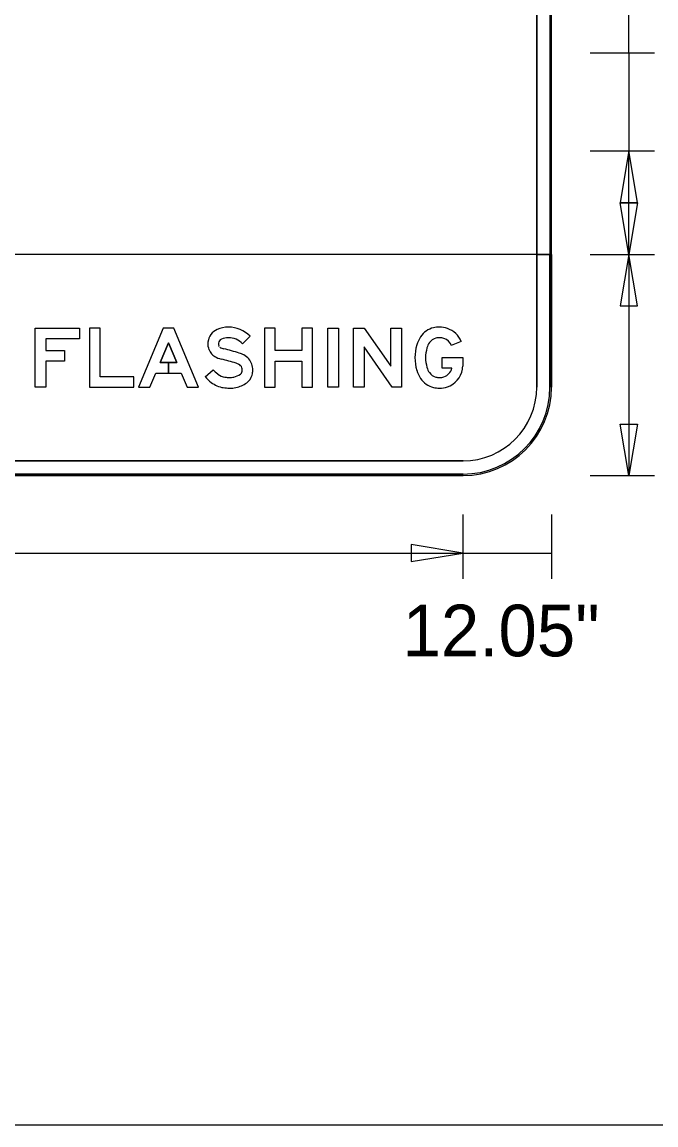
# Model space of a CAD drawing. Extents: x 17890071 to 17890754, y 17897628 to 17897992.
# Drawn here: x 17890204.8 to 17890211.96, y 17897794.28 to 17897806.75 of the extents above; entities that cross this region are included whole.
import ezdxf

# ---------------------------------------------------------------- set-up
doc = ezdxf.new("R2010")
doc.units = 0
for name, color, linetype in [('GSBWFill', 7, 'Continuous'), ('GSColorFill', 7, 'Continuous'), ('GSDims', 7, 'Continuous'), ('GSOutline', 7, 'Continuous'), ('SheetLinesMisc2_dp', 7, 'Continuous')]:
    doc.layers.add(name, color=color, linetype=linetype)

msp = doc.modelspace()

# ---------------------------------------------------------------- linework, layer by layer
at = {"layer": 'GSBWFill'}
for p, q in [((17890210.615, 17897810.621), (17890210.615, 17897802.621)), ((17890210.782, 17897802.621), (17890210.782, 17897810.621)), ((17890210.782, 17897804.121), (17890190.782, 17897804.121)), ((17890210.615, 17897803.954), (17890210.615, 17897804.121)), ((17890210.615, 17897804.121), (17890210.782, 17897804.121)), ((17890210.782, 17897804.121), (17890210.782, 17897802.621)), ((17890210.782, 17897802.621), (17890210.782, 17897804.121)), ((17890210.615, 17897802.621), (17890210.615, 17897803.954)), ((17890191.782, 17897801.788), (17890209.782, 17897801.788)), ((17890209.782, 17897801.788), (17890191.783, 17897801.788)), ((17890209.782, 17897801.621), (17890191.782, 17897801.621)), ((17890191.782, 17897801.621), (17890209.782, 17897801.621)), ((17890191.783, 17897801.621), (17890209.782, 17897801.621))]:
    msp.add_line(p, q, dxfattribs=at)
for points in [[(17890205.065, 17897802.914), (17890205.065, 17897802.621), (17890204.945, 17897802.621), (17890204.945, 17897803.288), (17890205.445, 17897803.288), (17890205.445, 17897803.168), (17890205.065, 17897803.168), (17890205.065, 17897803.034), (17890205.275, 17897803.034), (17890205.275, 17897802.914)], [(17890206.058, 17897802.621), (17890206.058, 17897802.738), (17890205.678, 17897802.738), (17890205.678, 17897803.288), (17890205.558, 17897803.288), (17890205.558, 17897802.621)], [(17890206.545, 17897802.898), (17890206.452, 17897802.898), (17890206.452, 17897802.778), (17890206.596, 17897802.778), (17890206.662, 17897802.621), (17890206.792, 17897802.621), (17890206.512, 17897803.288), (17890206.392, 17897803.288), (17890206.112, 17897802.621), (17890206.242, 17897802.621), (17890206.308, 17897802.778), (17890206.452, 17897802.778), (17890206.452, 17897802.898), (17890206.358, 17897802.898), (17890206.452, 17897803.121)], [(17890207.958, 17897803.034), (17890207.658, 17897803.034), (17890207.658, 17897803.288), (17890207.538, 17897803.288), (17890207.538, 17897802.621), (17890207.658, 17897802.621), (17890207.658, 17897802.914), (17890207.958, 17897802.914), (17890207.958, 17897802.621), (17890208.078, 17897802.621), (17890208.078, 17897803.288), (17890207.958, 17897803.288)], [(17890208.252, 17897802.621), (17890208.252, 17897803.288), (17890208.372, 17897803.288), (17890208.372, 17897802.621)], [(17890209.085, 17897803.288), (17890209.085, 17897802.621), (17890208.982, 17897802.621), (17890208.665, 17897803.078), (17890208.665, 17897802.621), (17890208.545, 17897802.621), (17890208.545, 17897803.288), (17890208.665, 17897803.288), (17890208.965, 17897802.856), (17890208.965, 17897803.288)]]:
    msp.add_lwpolyline(points, close=True, dxfattribs=at)
for points in [[(17890207.374, 17897803.196), (17890207.289, 17897803.112)], [(17890209.76, 17897803.136), (17890209.649, 17897803.091)], [(17890209.655, 17897802.834), (17890209.545, 17897802.834), (17890209.545, 17897802.954), (17890209.778, 17897802.954), (17890209.778, 17897802.858)], [(17890206.865, 17897802.739), (17890206.956, 17897802.817)]]:
    msp.add_lwpolyline(points, dxfattribs=at)
for centre, radius, start, end in [((17890207.071, 17897803.113), 0.174, 113.3248, 174.1421), ((17890207.128, 17897802.981), 0.318, 90, 113.3248), ((17890207.128, 17897802.954), 0.345, 44.4342, 90), ((17890209.503, 17897803.058), 0.24, 103.1315, 146.7742), ((17890209.514, 17897803.01), 0.289, 90, 103.1315), ((17890209.514, 17897803.019), 0.28, 71.2015, 90), ((17890209.521, 17897803.039), 0.259, 22.0367, 71.2015), ((17890207.087, 17897803.111), 0.191, 174.1421, 201.2247), ((17890207.071, 17897803.113), 0.0543, 113.3248, 174.1421), ((17890207.087, 17897803.111), 0.0706, 174.1421, 201.2247), ((17890207.049, 17897803.096), 0.029, 201.2247, 240.1812), ((17890207.128, 17897802.981), 0.198, 90, 113.3248), ((17890207.128, 17897802.954), 0.225, 44.4342, 90), ((17890209.743, 17897802.954), 0.505, 163.4624, 180), ((17890209.592, 17897802.999), 0.348, 146.7742, 163.4624), ((17890209.592, 17897802.999), 0.228, 146.7742, 163.4624), ((17890209.503, 17897803.058), 0.12, 103.1315, 146.7742), ((17890209.514, 17897803.01), 0.169, 90, 103.1315), ((17890209.514, 17897803.019), 0.16, 71.2015, 90), ((17890209.521, 17897803.039), 0.139, 22.0367, 71.2015), ((17890207.049, 17897803.096), 0.149, 201.2247, 240.1812), ((17890207.117, 17897803.217), 0.288, 240.1812, 256.1067), ((17890207.117, 17897803.217), 0.168, 240.1812, 256.1067), ((17890206.3, 17897799.913), 3.236, 72.8961, 76.1067), ((17890207.158, 17897802.7), 0.32, 63.0108, 72.8961), ((17890207.222, 17897802.826), 0.178, 39.5561, 63.0108), ((17890209.743, 17897802.954), 0.505, 180, 196.5376), ((17890209.743, 17897802.954), 0.385, 163.4624, 180), ((17890209.743, 17897802.954), 0.385, 180, 196.5376), ((17890206.3, 17897799.913), 3.116, 72.8961, 76.1067), ((17890207.158, 17897802.7), 0.2, 63.0108, 72.8961), ((17890207.222, 17897802.826), 0.0579, 39.5561, 63.0108), ((17890207.206, 17897802.813), 0.0794, 0, 39.5561), ((17890207.206, 17897802.813), 0.199, 0, 39.5561), ((17890209.592, 17897802.91), 0.228, 196.5376, 213.2258), ((17890209.521, 17897802.869), 0.139, 288.7985, 345.418), ((17890209.58, 17897802.858), 0.198, 349.6765, 0), ((17890207.216, 17897803.043), 0.464, 220.8202, 232.6492), ((17890207.216, 17897803.043), 0.344, 220.8202, 232.6492), ((17890207.12, 17897802.916), 0.185, 232.6492, 260.7349), ((17890207.14, 17897803.04), 0.31, 260.7349, 270), ((17890207.14, 17897802.974), 0.245, 270, 281.6446), ((17890207.15, 17897802.926), 0.196, 281.6446, 306.0677), ((17890207.239, 17897802.804), 0.045, 306.0677, 343.4972), ((17890207.21, 17897802.813), 0.0746, 343.4972, 0), ((17890207.239, 17897802.804), 0.165, 306.0677, 343.4972), ((17890207.21, 17897802.813), 0.195, 343.4972, 0), ((17890209.592, 17897802.91), 0.348, 196.5376, 213.2258), ((17890209.503, 17897802.851), 0.24, 213.2258, 256.8685), ((17890209.503, 17897802.851), 0.12, 213.2258, 256.8685), ((17890209.514, 17897802.899), 0.169, 256.8685, 270), ((17890209.514, 17897802.889), 0.16, 270, 288.7985), ((17890209.521, 17897802.869), 0.259, 288.7985, 349.6765), ((17890207.12, 17897802.916), 0.305, 232.6492, 260.7349), ((17890207.14, 17897803.04), 0.43, 260.7349, 270), ((17890207.14, 17897802.974), 0.365, 270, 281.6446), ((17890207.15, 17897802.926), 0.316, 281.6446, 306.0677), ((17890209.514, 17897802.899), 0.289, 256.8685, 270), ((17890209.514, 17897802.889), 0.28, 270, 288.7985), ((17890209.782, 17897802.621), 1, 270, 0), ((17890209.782, 17897802.621), 0.833, 270, 0), ((17890209.782, 17897802.621), 1, 270, 0), ((17890209.782, 17897802.621), 0.833, 270, 0), ((17890209.782, 17897802.621), 1, 270, 0)]:
    msp.add_arc(centre, radius, start, end, dxfattribs=at)
at = {"layer": 'GSColorFill'}
for p, q in [((17890210.615, 17897810.621), (17890210.615, 17897802.621)), ((17890210.765, 17897810.621), (17890210.765, 17897802.621)), ((17890210.782, 17897802.621), (17890210.782, 17897810.621)), ((17890210.782, 17897802.621), (17890210.782, 17897810.621)), ((17890210.782, 17897802.621), (17890210.782, 17897810.621)), ((17890210.782, 17897804.121), (17890190.782, 17897804.121)), ((17890210.615, 17897803.954), (17890210.615, 17897804.121)), ((17890210.615, 17897804.121), (17890210.782, 17897804.121)), ((17890210.765, 17897804.104), (17890210.765, 17897804.121)), ((17890210.765, 17897804.121), (17890210.782, 17897804.121)), ((17890210.765, 17897802.621), (17890210.765, 17897804.104)), ((17890210.782, 17897802.621), (17890210.782, 17897804.121)), ((17890210.782, 17897804.121), (17890210.782, 17897802.621)), ((17890210.782, 17897804.121), (17890210.782, 17897802.621)), ((17890210.615, 17897802.621), (17890210.615, 17897803.954)), ((17890191.782, 17897801.788), (17890209.782, 17897801.788)), ((17890209.782, 17897801.788), (17890191.783, 17897801.788)), ((17890209.782, 17897801.638), (17890191.782, 17897801.638)), ((17890191.782, 17897801.638), (17890209.782, 17897801.638)), ((17890191.782, 17897801.621), (17890209.782, 17897801.621)), ((17890191.782, 17897801.621), (17890209.782, 17897801.621)), ((17890191.782, 17897801.621), (17890209.782, 17897801.621)), ((17890209.782, 17897801.621), (17890191.782, 17897801.621)), ((17890209.782, 17897801.621), (17890191.782, 17897801.621)), ((17890191.783, 17897801.621), (17890209.782, 17897801.621))]:
    msp.add_line(p, q, dxfattribs=at)
for points in [[(17890205.065, 17897802.914), (17890205.065, 17897802.621), (17890204.945, 17897802.621), (17890204.945, 17897803.288), (17890205.445, 17897803.288), (17890205.445, 17897803.168), (17890205.065, 17897803.168), (17890205.065, 17897803.034), (17890205.275, 17897803.034), (17890205.275, 17897802.914)], [(17890206.058, 17897802.621), (17890206.058, 17897802.738), (17890205.678, 17897802.738), (17890205.678, 17897803.288), (17890205.558, 17897803.288), (17890205.558, 17897802.621)], [(17890206.545, 17897802.898), (17890206.452, 17897802.898), (17890206.452, 17897802.778), (17890206.596, 17897802.778), (17890206.662, 17897802.621), (17890206.792, 17897802.621), (17890206.512, 17897803.288), (17890206.392, 17897803.288), (17890206.112, 17897802.621), (17890206.242, 17897802.621), (17890206.308, 17897802.778), (17890206.452, 17897802.778), (17890206.452, 17897802.898), (17890206.358, 17897802.898), (17890206.452, 17897803.121)], [(17890207.958, 17897803.034), (17890207.658, 17897803.034), (17890207.658, 17897803.288), (17890207.538, 17897803.288), (17890207.538, 17897802.621), (17890207.658, 17897802.621), (17890207.658, 17897802.914), (17890207.958, 17897802.914), (17890207.958, 17897802.621), (17890208.078, 17897802.621), (17890208.078, 17897803.288), (17890207.958, 17897803.288)], [(17890208.252, 17897802.621), (17890208.252, 17897803.288), (17890208.372, 17897803.288), (17890208.372, 17897802.621)], [(17890209.085, 17897803.288), (17890209.085, 17897802.621), (17890208.982, 17897802.621), (17890208.665, 17897803.078), (17890208.665, 17897802.621), (17890208.545, 17897802.621), (17890208.545, 17897803.288), (17890208.665, 17897803.288), (17890208.965, 17897802.856), (17890208.965, 17897803.288)]]:
    msp.add_lwpolyline(points, close=True, dxfattribs=at)
for points in [[(17890207.374, 17897803.196), (17890207.289, 17897803.112)], [(17890209.76, 17897803.136), (17890209.649, 17897803.091)], [(17890209.655, 17897802.834), (17890209.545, 17897802.834), (17890209.545, 17897802.954), (17890209.778, 17897802.954), (17890209.778, 17897802.858)], [(17890206.865, 17897802.739), (17890206.956, 17897802.817)]]:
    msp.add_lwpolyline(points, dxfattribs=at)
for centre, radius, start, end in [((17890207.071, 17897803.113), 0.174, 113.3248, 174.1421), ((17890207.128, 17897802.981), 0.318, 90, 113.3248), ((17890207.128, 17897802.954), 0.345, 44.4342, 90), ((17890209.503, 17897803.058), 0.24, 103.1315, 146.7742), ((17890209.514, 17897803.01), 0.289, 90, 103.1315), ((17890209.514, 17897803.019), 0.28, 71.2015, 90), ((17890209.521, 17897803.039), 0.259, 22.0367, 71.2015), ((17890207.087, 17897803.111), 0.191, 174.1421, 201.2247), ((17890207.071, 17897803.113), 0.0543, 113.3248, 174.1421), ((17890207.087, 17897803.111), 0.0706, 174.1421, 201.2247), ((17890207.049, 17897803.096), 0.029, 201.2247, 240.1812), ((17890207.128, 17897802.981), 0.198, 90, 113.3248), ((17890207.128, 17897802.954), 0.225, 44.4342, 90), ((17890209.743, 17897802.954), 0.505, 163.4624, 180), ((17890209.592, 17897802.999), 0.348, 146.7742, 163.4624), ((17890209.592, 17897802.999), 0.228, 146.7742, 163.4624), ((17890209.503, 17897803.058), 0.12, 103.1315, 146.7742), ((17890209.514, 17897803.01), 0.169, 90, 103.1315), ((17890209.514, 17897803.019), 0.16, 71.2015, 90), ((17890209.521, 17897803.039), 0.139, 22.0367, 71.2015), ((17890207.049, 17897803.096), 0.149, 201.2247, 240.1812), ((17890207.117, 17897803.217), 0.288, 240.1812, 256.1067), ((17890207.117, 17897803.217), 0.168, 240.1812, 256.1067), ((17890206.3, 17897799.913), 3.236, 72.8961, 76.1067), ((17890207.158, 17897802.7), 0.32, 63.0108, 72.8961), ((17890207.222, 17897802.826), 0.178, 39.5561, 63.0108), ((17890209.743, 17897802.954), 0.505, 180, 196.5376), ((17890209.743, 17897802.954), 0.385, 163.4624, 180), ((17890209.743, 17897802.954), 0.385, 180, 196.5376), ((17890206.3, 17897799.913), 3.116, 72.8961, 76.1067), ((17890207.158, 17897802.7), 0.2, 63.0108, 72.8961), ((17890207.222, 17897802.826), 0.0579, 39.5561, 63.0108), ((17890207.206, 17897802.813), 0.0794, 0, 39.5561), ((17890207.206, 17897802.813), 0.199, 0, 39.5561), ((17890209.592, 17897802.91), 0.228, 196.5376, 213.2258), ((17890209.521, 17897802.869), 0.139, 288.7985, 345.418), ((17890209.58, 17897802.858), 0.198, 349.6765, 0), ((17890207.216, 17897803.043), 0.464, 220.8202, 232.6492), ((17890207.216, 17897803.043), 0.344, 220.8202, 232.6492), ((17890207.12, 17897802.916), 0.185, 232.6492, 260.7349), ((17890207.14, 17897803.04), 0.31, 260.7349, 270), ((17890207.14, 17897802.974), 0.245, 270, 281.6446), ((17890207.15, 17897802.926), 0.196, 281.6446, 306.0677), ((17890207.239, 17897802.804), 0.045, 306.0677, 343.4972), ((17890207.21, 17897802.813), 0.0746, 343.4972, 0), ((17890207.239, 17897802.804), 0.165, 306.0677, 343.4972), ((17890207.21, 17897802.813), 0.195, 343.4972, 0), ((17890209.592, 17897802.91), 0.348, 196.5376, 213.2258), ((17890209.503, 17897802.851), 0.24, 213.2258, 256.8685), ((17890209.503, 17897802.851), 0.12, 213.2258, 256.8685), ((17890209.514, 17897802.899), 0.169, 256.8685, 270), ((17890209.514, 17897802.889), 0.16, 270, 288.7985), ((17890209.521, 17897802.869), 0.259, 288.7985, 349.6765), ((17890207.12, 17897802.916), 0.305, 232.6492, 260.7349), ((17890207.14, 17897803.04), 0.43, 260.7349, 270), ((17890207.14, 17897802.974), 0.365, 270, 281.6446), ((17890207.15, 17897802.926), 0.316, 281.6446, 306.0677), ((17890209.514, 17897802.899), 0.289, 256.8685, 270), ((17890209.514, 17897802.889), 0.28, 270, 288.7985), ((17890209.782, 17897802.621), 1, 270, 0), ((17890209.782, 17897802.621), 1, 270, 0), ((17890209.782, 17897802.621), 0.833, 270, 0), ((17890209.782, 17897802.621), 1, 270, 0), ((17890209.782, 17897802.621), 0.983, 270, 0), ((17890209.782, 17897802.621), 1, 270, 0), ((17890209.782, 17897802.621), 1, 270, 0), ((17890209.782, 17897802.621), 0.833, 270, 0), ((17890209.782, 17897802.621), 1, 270, 0), ((17890209.782, 17897802.621), 0.983, 270, 0)]:
    msp.add_arc(centre, radius, start, end, dxfattribs=at)
at = {"layer": 'GSDims'}
for p, q in [((17890211.657, 17897806.4), (17890211.657, 17897807.233)), ((17890211.219, 17897806.4), (17890211.948, 17897806.4)), ((17890211.219, 17897806.4), (17890211.948, 17897806.4)), ((17890211.657, 17897806.4), (17890211.657, 17897805.292)), ((17890211.219, 17897805.292), (17890211.948, 17897805.292)), ((17890211.219, 17897805.292), (17890211.948, 17897805.292)), ((17890211.657, 17897804.121), (17890211.657, 17897805.292)), ((17890211.219, 17897804.121), (17890211.948, 17897804.121)), ((17890211.219, 17897804.121), (17890211.948, 17897804.121)), ((17890211.657, 17897804.121), (17890211.657, 17897801.621)), ((17890211.219, 17897801.621), (17890211.948, 17897801.621)), ((17890209.778, 17897801.183), (17890209.778, 17897800.454)), ((17890209.778, 17897801.183), (17890209.778, 17897800.454)), ((17890210.782, 17897801.183), (17890210.782, 17897800.454)), ((17890191.785, 17897800.746), (17890209.778, 17897800.746)), ((17890209.778, 17897800.746), (17890210.782, 17897800.746))]:
    msp.add_line(p, q, dxfattribs=at)
for points in [[(17890211.657, 17897805.292), (17890211.559, 17897804.708), (17890211.754, 17897804.708)], [(17890211.657, 17897804.121), (17890211.559, 17897804.704), (17890211.754, 17897804.704)], [(17890211.657, 17897804.121), (17890211.559, 17897803.538), (17890211.754, 17897803.538)], [(17890211.657, 17897801.621), (17890211.559, 17897802.204), (17890211.754, 17897802.204)], [(17890209.778, 17897800.746), (17890209.195, 17897800.843), (17890209.195, 17897800.649)]]:
    msp.add_lwpolyline(points, close=True, dxfattribs=at)
at = {"layer": 'GSOutline'}
for p, q in [((17890210.615, 17897802.621), (17890210.615, 17897810.621)), ((17890210.782, 17897802.621), (17890210.782, 17897810.621)), ((17890210.782, 17897804.121), (17890190.782, 17897804.121)), ((17890210.615, 17897803.954), (17890210.615, 17897804.121)), ((17890210.615, 17897804.121), (17890210.782, 17897804.121)), ((17890210.782, 17897804.121), (17890210.782, 17897802.621)), ((17890210.782, 17897802.621), (17890210.782, 17897804.121)), ((17890210.615, 17897802.621), (17890210.615, 17897803.954)), ((17890191.782, 17897801.788), (17890209.782, 17897801.788)), ((17890191.782, 17897801.788), (17890209.782, 17897801.788)), ((17890191.782, 17897801.621), (17890209.782, 17897801.621)), ((17890209.782, 17897801.621), (17890191.782, 17897801.621)), ((17890191.782, 17897801.621), (17890209.782, 17897801.621))]:
    msp.add_line(p, q, dxfattribs=at)
for points in [[(17890205.065, 17897802.914), (17890205.065, 17897802.621), (17890204.945, 17897802.621), (17890204.945, 17897803.288), (17890205.445, 17897803.288), (17890205.445, 17897803.168), (17890205.065, 17897803.168), (17890205.065, 17897803.034), (17890205.275, 17897803.034), (17890205.275, 17897802.914)], [(17890206.058, 17897802.621), (17890206.058, 17897802.738), (17890205.678, 17897802.738), (17890205.678, 17897803.288), (17890205.558, 17897803.288), (17890205.558, 17897802.621)], [(17890206.308, 17897802.778), (17890206.596, 17897802.778), (17890206.662, 17897802.621), (17890206.792, 17897802.621), (17890206.512, 17897803.288), (17890206.392, 17897803.288), (17890206.112, 17897802.621), (17890206.242, 17897802.621)], [(17890207.958, 17897803.034), (17890207.658, 17897803.034), (17890207.658, 17897803.288), (17890207.538, 17897803.288), (17890207.538, 17897802.621), (17890207.658, 17897802.621), (17890207.658, 17897802.914), (17890207.958, 17897802.914), (17890207.958, 17897802.621), (17890208.078, 17897802.621), (17890208.078, 17897803.288), (17890207.958, 17897803.288)], [(17890208.252, 17897802.621), (17890208.252, 17897803.288), (17890208.372, 17897803.288), (17890208.372, 17897802.621)], [(17890209.085, 17897803.288), (17890209.085, 17897802.621), (17890208.982, 17897802.621), (17890208.665, 17897803.078), (17890208.665, 17897802.621), (17890208.545, 17897802.621), (17890208.545, 17897803.288), (17890208.665, 17897803.288), (17890208.965, 17897802.856), (17890208.965, 17897803.288)], [(17890206.545, 17897802.898), (17890206.452, 17897803.121), (17890206.358, 17897802.898)]]:
    msp.add_lwpolyline(points, close=True, dxfattribs=at)
for points in [[(17890207.374, 17897803.196), (17890207.289, 17897803.112)], [(17890209.76, 17897803.136), (17890209.649, 17897803.091)], [(17890209.655, 17897802.834), (17890209.545, 17897802.834), (17890209.545, 17897802.954), (17890209.778, 17897802.954), (17890209.778, 17897802.858)], [(17890206.865, 17897802.739), (17890206.956, 17897802.817)]]:
    msp.add_lwpolyline(points, dxfattribs=at)
for centre, radius, start, end in [((17890207.071, 17897803.113), 0.174, 113.3248, 174.1421), ((17890207.128, 17897802.981), 0.318, 90, 113.3248), ((17890207.128, 17897802.954), 0.345, 44.4342, 90), ((17890209.503, 17897803.058), 0.24, 103.1315, 146.7742), ((17890209.514, 17897803.01), 0.289, 90, 103.1315), ((17890209.514, 17897803.019), 0.28, 71.2015, 90), ((17890209.521, 17897803.039), 0.259, 22.0367, 71.2015), ((17890207.087, 17897803.111), 0.191, 174.1421, 201.2247), ((17890207.071, 17897803.113), 0.0543, 113.3248, 174.1421), ((17890207.087, 17897803.111), 0.0706, 174.1421, 201.2247), ((17890207.049, 17897803.096), 0.029, 201.2247, 240.1812), ((17890207.128, 17897802.981), 0.198, 90, 113.3248), ((17890207.128, 17897802.954), 0.225, 44.4342, 90), ((17890209.743, 17897802.954), 0.505, 163.4624, 180), ((17890209.592, 17897802.999), 0.348, 146.7742, 163.4624), ((17890209.592, 17897802.999), 0.228, 146.7742, 163.4624), ((17890209.503, 17897803.058), 0.12, 103.1315, 146.7742), ((17890209.514, 17897803.01), 0.169, 90, 103.1315), ((17890209.514, 17897803.019), 0.16, 71.2015, 90), ((17890209.521, 17897803.039), 0.139, 22.0367, 71.2015), ((17890207.049, 17897803.096), 0.149, 201.2247, 240.1812), ((17890207.117, 17897803.217), 0.288, 240.1812, 256.1067), ((17890207.117, 17897803.217), 0.168, 240.1812, 256.1067), ((17890206.3, 17897799.913), 3.236, 72.8961, 76.1067), ((17890207.158, 17897802.7), 0.32, 63.0108, 72.8961), ((17890207.222, 17897802.826), 0.178, 39.5561, 63.0108), ((17890209.743, 17897802.954), 0.505, 180, 196.5376), ((17890209.743, 17897802.954), 0.385, 163.4624, 180), ((17890209.743, 17897802.954), 0.385, 180, 196.5376), ((17890206.3, 17897799.913), 3.116, 72.8961, 76.1067), ((17890207.158, 17897802.7), 0.2, 63.0108, 72.8961), ((17890207.222, 17897802.826), 0.0579, 39.5561, 63.0108), ((17890207.206, 17897802.813), 0.0794, 0, 39.5561), ((17890207.206, 17897802.813), 0.199, 0, 39.5561), ((17890209.592, 17897802.91), 0.228, 196.5376, 213.2258), ((17890209.521, 17897802.869), 0.139, 288.7985, 345.418), ((17890209.58, 17897802.858), 0.198, 349.6765, 0), ((17890207.216, 17897803.043), 0.464, 220.8202, 232.6492), ((17890207.216, 17897803.043), 0.344, 220.8202, 232.6492), ((17890207.12, 17897802.916), 0.185, 232.6492, 260.7349), ((17890207.14, 17897803.04), 0.31, 260.7349, 270), ((17890207.14, 17897802.974), 0.245, 270, 281.6446), ((17890207.15, 17897802.926), 0.196, 281.6446, 306.0677), ((17890207.239, 17897802.804), 0.045, 306.0677, 343.4972), ((17890207.21, 17897802.813), 0.0746, 343.4972, 0), ((17890207.239, 17897802.804), 0.165, 306.0677, 343.4972), ((17890207.21, 17897802.813), 0.195, 343.4972, 0), ((17890209.592, 17897802.91), 0.348, 196.5376, 213.2258), ((17890209.503, 17897802.851), 0.24, 213.2258, 256.8685), ((17890209.503, 17897802.851), 0.12, 213.2258, 256.8685), ((17890209.514, 17897802.899), 0.169, 256.8685, 270), ((17890209.514, 17897802.889), 0.16, 270, 288.7985), ((17890209.521, 17897802.869), 0.259, 288.7985, 349.6765), ((17890207.12, 17897802.916), 0.305, 232.6492, 260.7349), ((17890207.14, 17897803.04), 0.43, 260.7349, 270), ((17890207.14, 17897802.974), 0.365, 270, 281.6446), ((17890207.15, 17897802.926), 0.316, 281.6446, 306.0677), ((17890209.514, 17897802.899), 0.289, 256.8685, 270), ((17890209.514, 17897802.889), 0.28, 270, 288.7985), ((17890209.782, 17897802.621), 1, 270, 0), ((17890209.782, 17897802.621), 0.833, 270, 0), ((17890209.782, 17897802.621), 1, 270, 0), ((17890209.782, 17897802.621), 0.833, 270, 0), ((17890209.782, 17897802.621), 1, 270, 0)]:
    msp.add_arc(centre, radius, start, end, dxfattribs=at)
at = {"layer": 'SheetLinesMisc2_dp'}
msp.add_line((17890175.209, 17897794.284), (17890226.38, 17897794.284), dxfattribs=at)

# ---------------------------------------------------------------- texts
at = {"layer": 'GSDims'}
msp.add_text('12.05"', height=0.5833, dxfattribs=at).set_placement((17890209.098, 17897799.579))

doc.saveas('drawing.dxf')
